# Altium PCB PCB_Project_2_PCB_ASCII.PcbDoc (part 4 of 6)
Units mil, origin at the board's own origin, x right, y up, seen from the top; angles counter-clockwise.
Board outline 3900 x 7800 mil, 6 copper layers (Top Layer, GND 1, Signal, Power, GND 2, Bottom Layer), stack 62.1 mil thick; 636 components, 334 nets, 1830 pads, 1401 vias.
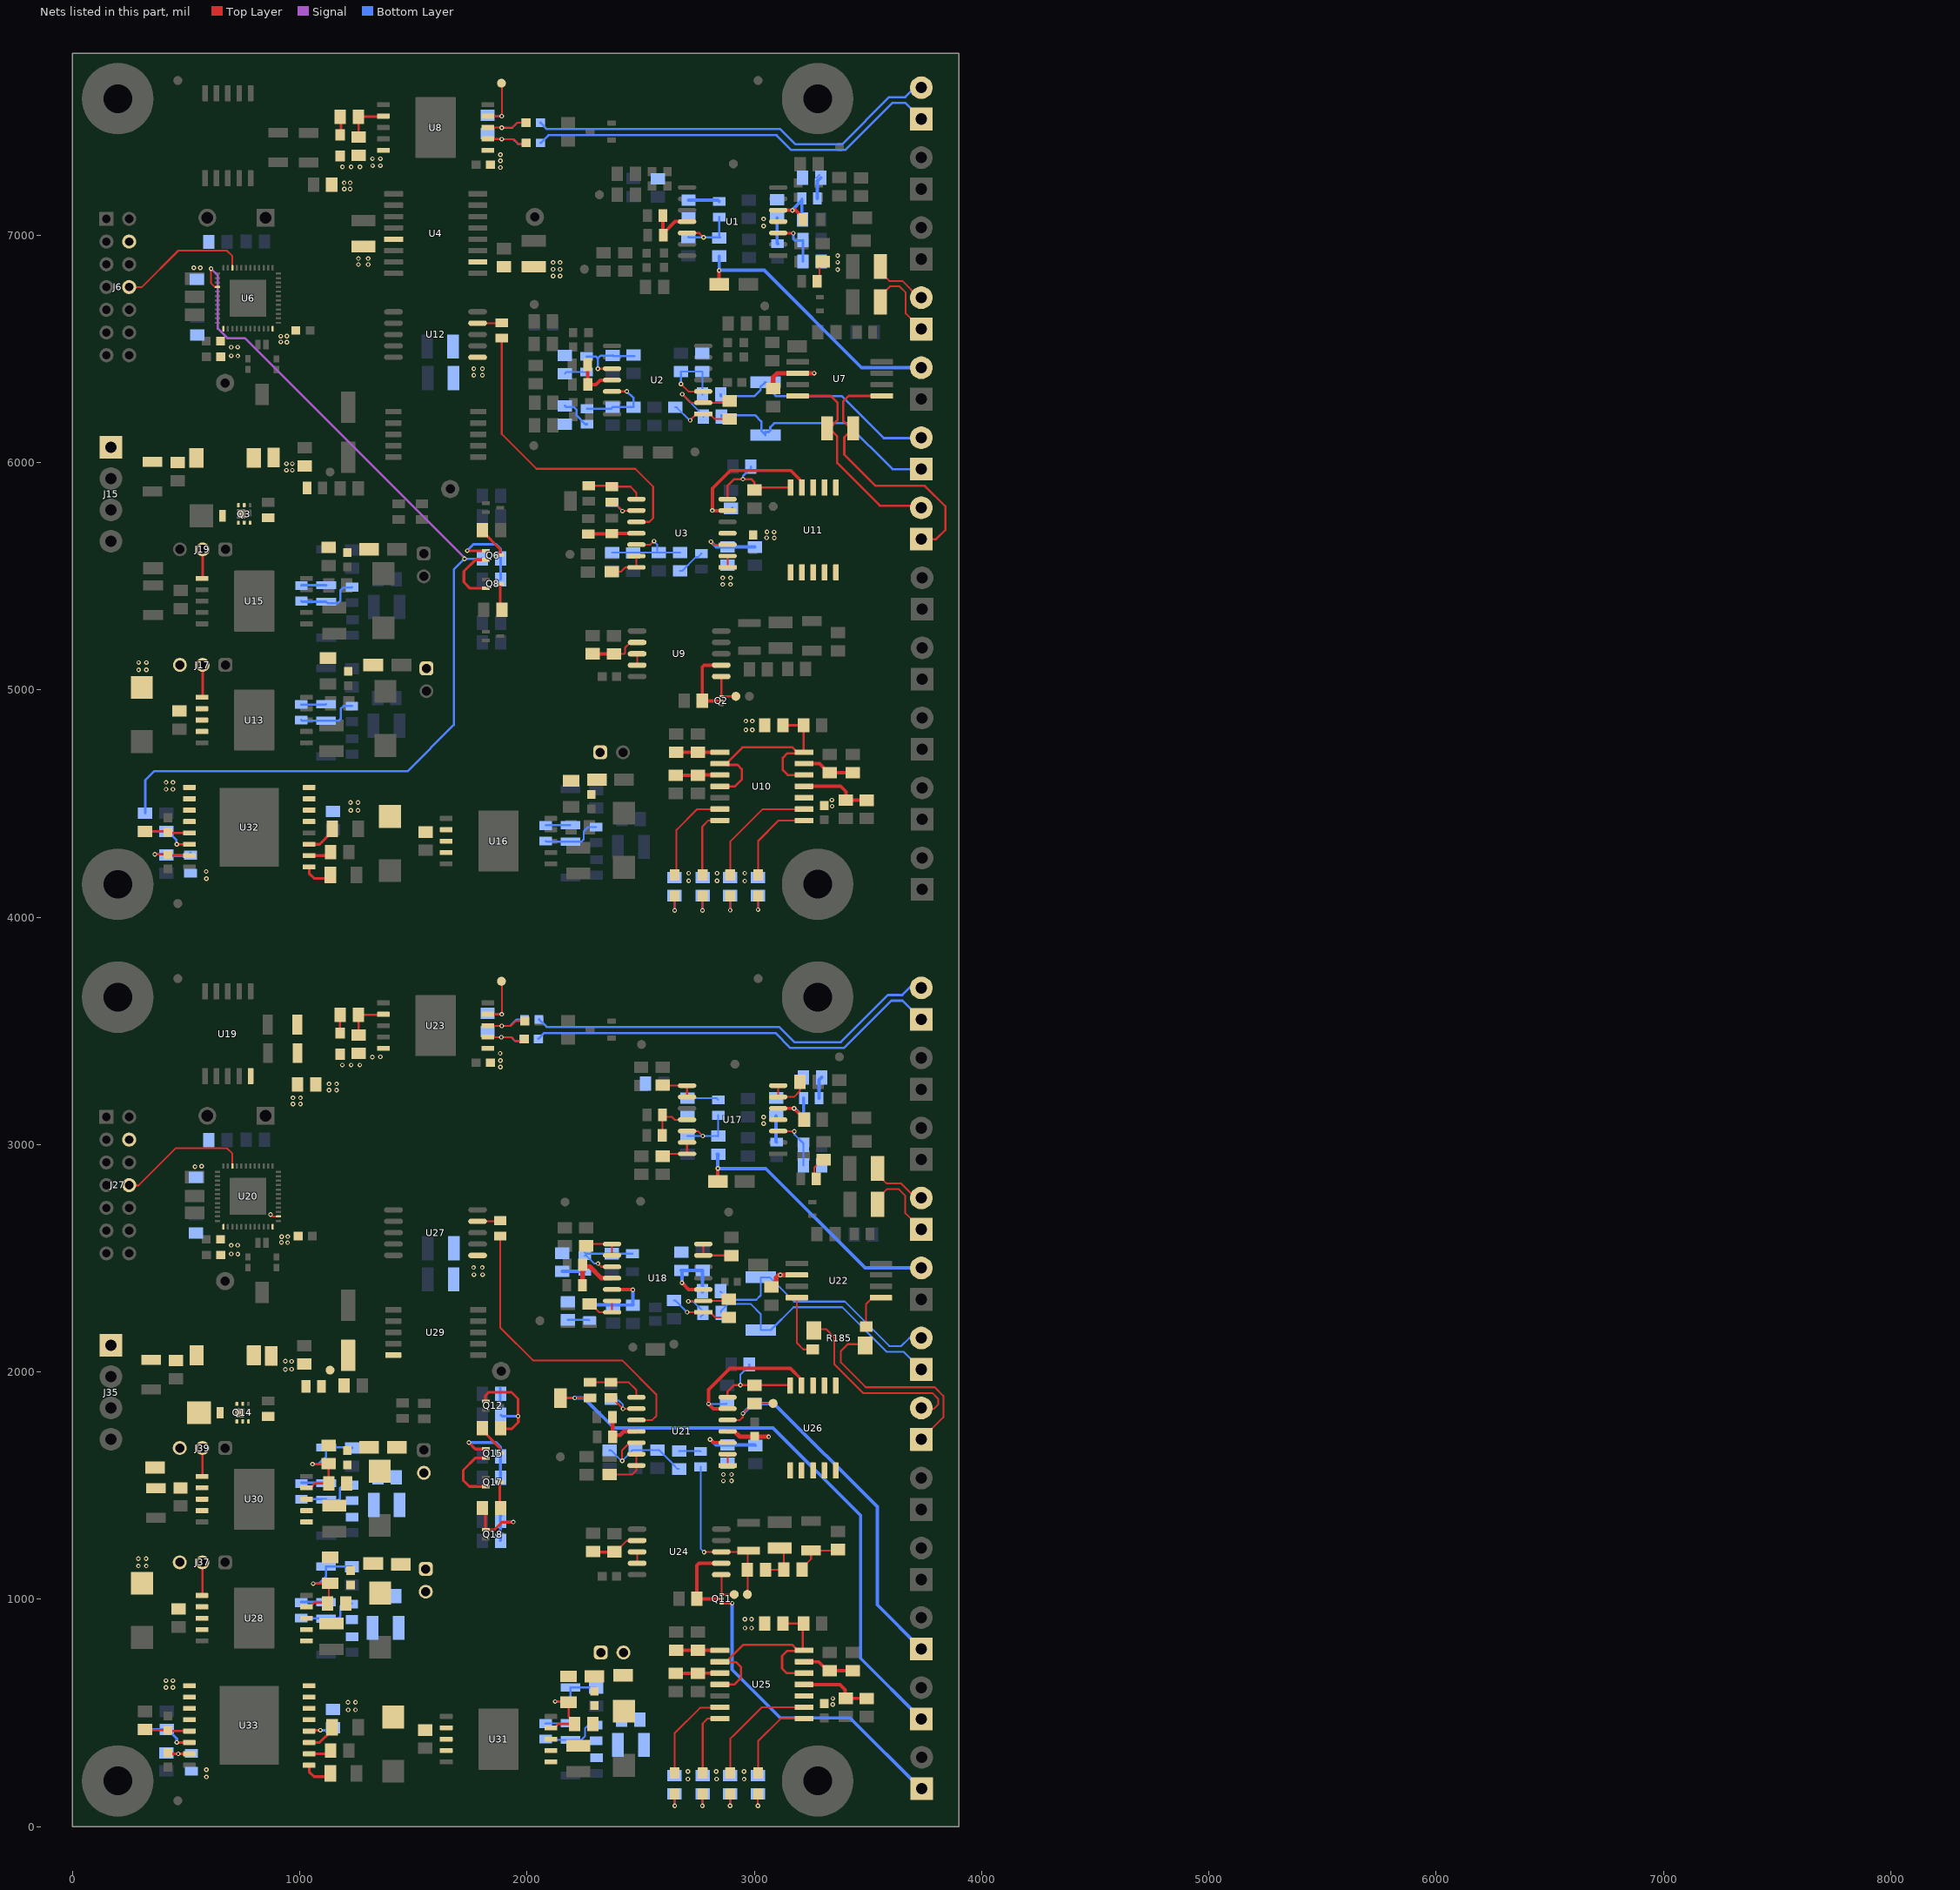
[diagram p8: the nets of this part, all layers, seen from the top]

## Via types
v1: diameter 20, hole 10, Top Layer to Bottom Layer, tented both sides, 1161 vias
v2: diameter 19.68, hole 7.87, Top Layer to Bottom Layer, 240 vias

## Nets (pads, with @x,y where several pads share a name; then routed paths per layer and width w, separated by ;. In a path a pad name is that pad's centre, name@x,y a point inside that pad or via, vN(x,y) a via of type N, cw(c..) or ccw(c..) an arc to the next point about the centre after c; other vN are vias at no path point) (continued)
NetC95_2: C95.2 R204.2 R206.2 TP57.1 U24.3 | length 793.4
  Top Layer w8: v1(2779.66,1207.33) 2780.26,1207.93 2848.17,1207.93 2854.71,1214.47 U24.3@2860.65,1208.53 ; U24.3@2854.71,1208.53 U24.3@2860.65,1208.53 ; R204.2@2970.75,1133.31 C95.2@2970.75,1214.47 ; TP57.1@2970.79,1010.82 TP57.1@2970.91,1010.94 ; TP57.1@2970.91,1019.89 2970.91,1127.69 2970.91,1133.31 R204.2@2972.21,1134.62 ; C95.2@2975.28,1214.47 C95.2@2970.75,1214.47 ; R204.2@2984.42,1141.46 R204.2@2988.43,1137.45 ; U24.3@2860.65,1208.53 2964.81,1208.53 C95.2@2970.75,1214.47
  Bottom Layer w8: R206.2@2764.02,1582.55 2764.02,1222.97 v1(2779.66,1207.33)
NetC96_1: C96.1 R202.2 R203.1 | length 220.9
  Top Layer w8: R203.1@3217.22,1137.66 3217.22,1144.55 3249.6,1176.93 3249.6,1213.81 C96.1@3250.22,1214.44 ; C96.1@3253.84,1222.04 C96.1@3257.62,1218.26 ; C96.1@3257.62,1214.44 C96.1@3257.62,1218.26 ; R202.2@3370.37,1231.17 3353.63,1214.44 3261.44,1214.44 C96.1@3257.62,1218.26
NetC97_1: C97.1 R203.2 R204.1 | length 184.3
  Top Layer w8: R204.1@3049.81,1129.86 3130.58,1129.86 R203.2@3130.78,1130.06 3130.78,1207.14 C97.1@3112.3,1225.62
NetC102_1: C102.1 R236.1 R237.1 TP62.1 U29.10
NetC104_1: C104.1 C105.1 C106.1 C107.1 C108.1 J36.2 R238.2 TP63.1 U28.6 U28.7 U28.8
NetC104_2: C104.2 D18.2 R239.1 R243.2 U28.9 | length 491
  Top Layer w8: C104.2@1128.04,984.27 1128.04,1063.82 1133.1,1068.88 R239.1@1134.69,1070.47
  Top Layer w10: U28.9@1029.99,966.93 1047.12,966.93 1065.88,985.68 C104.2@1122.35,985.68 ; v1(1059.83,1068.88) R239.1@1133.1,1068.88
  Bottom Layer w10: v1(1059.83,1068.88) 1085.16,1068.88 1116.03,1099.75 1116.03,1144.44 D18.2@1116.21,1144.62 1227.84,1144.62 R243.2@1230.01,1142.46
NetC107_2: C107.2 C108.2 R241.1 R242.1
NetC111_1: C111.1 C112.1 C113.1 C114.1 C115.1 J38.2 R244.2 TP66.1 U30.6 U30.7 U30.8
NetC111_2: C111.2 D21.2 R246.1 R254.2 U30.9 | length 493.2
  Top Layer w10: U30.9@1030.71,1490.09 1047.84,1490.09 1067.47,1509.73 1127.14,1509.73 C111.2@1127.82,1509.05 1127.82,1595.74 R246.1@1127.05,1596.51 1125.05,1594.51 v1(1056.65,1594.51)
  Bottom Layer w10: v1(1056.65,1594.51) 1083.54,1594.51 1116.17,1627.14 1116.17,1667.03 D21.2@1116.93,1667.78 1228.56,1667.78 R254.2@1230.72,1665.62
NetC114_2: C114.2 C115.2 R249.1 R251.1
NetC116_2: C116.2 Q12.1 R245.1 R250.2 | length 552
  Top Layer w12: Q12.1@1817.29,1868.81 1816.75,1869.35 1816.75,1895.47 1831.8,1910.52 1932.28,1910.52 1960.89,1881.92 v1(1960.89,1805.46) 1962.06,1804.28 1962.06,1778.43 1934.13,1750.5 R250.2@1882.44,1750.5
  Bottom Layer w12: R245.1@1882.54,1837.92 C116.2@1882.54,1928.92 ; R245.1@1886,1810 1890.54,1805.46 v1(1960.89,1805.46)
NetC117_1: C117.1 R125.1 R127.2 U32.7 | length 322.3
  Top Layer w8: C117.1@420.09,4276.3 C117.1@420.72,4275.67
  Top Layer w10: v1(363.34,4276.3) C117.1@420.09,4276.3 ; C117.1@425.64,4270.75 U32.7@515.12,4270.75
  Top Layer w12: C117.1@420.72,4275.67 C117.1@425.64,4270.75
  Bottom Layer w8: R127.2@410.37,4276.3 R127.2@413.58,4273.09
  Bottom Layer w10: v1(363.34,4276.3) R127.2@410.37,4276.3
  Bottom Layer w12: R127.2@414.17,4284.17 427.6,4270.75 507.22,4270.75 R125.1@520.02,4283.54
NetC120_1: C120.1 C121.1 D20.1 J39.3 TP68.1 U30.2 U30.3 U30.4
NetC122_1: C122.1 Q18.1 R259.1 R260.2 | length 566.2
  Top Layer w12: R259.1@1801.57,1399.44 1817.29,1383.71 1817.29,1304.26 Q18.1@1821.18,1304.26 ; Q18.1@1819.44,1306 1856.73,1306 1888.67,1337.93 v1@1937.85,1337.93
  Bottom Layer w12: R260.2@1882.44,1282.82 1882.44,1369.31 C122.1@1886.62,1365.13 ; R260.2@1882.54,1282.69 1882.54,1369.18 C122.1@1886.72,1365 ; R260.2@1883.69,1257.45 1883.69,1343.94 1887.86,1339.76 v1@1939.65,1339.76
  other v1: 1940,1340.09
NetC123_1: C123.1 C124.1 C125.1 C126.1 C127.1 J40.2 R261.2 TP70.1 U31.6 U31.7 U31.8
NetC123_2: C123.2 D23.2 R262.1 R266.2 U31.9 | length 511.7
  Top Layer w10: U31.9@2104.9,434.68 2122.02,434.68 2139.57,452.23 C123.2@2209.59,452.23 2209.59,458.73 2183.45,484.87 2183.45,546.66 R262.1@2183.74,546.95 2180.32,550.38 v1(2123.84,550.38)
  Bottom Layer w10: v1(2123.84,550.38) 2171.99,550.38 2191.12,569.51 D23.2@2191.12,612.38 2302.75,612.38 R266.2@2304.91,610.22
NetC126_2: C126.2 C127.2 R264.1 R265.1
NetC130_1: C130.1 U32.11 | length 133.9
  Top Layer w12: U32.11@1042.12,4320.75 1088.27,4320.75 1135.71,4368.19 C130.1@1135.71,4388.88
NetC131_1: C131.1 U32.9 | length 137.3
  Top Layer w12: U32.9@1042.12,4220.75 1042.12,4192.03 1063.77,4170.38 1121.09,4170.38 C131.1@1135.71,4185
NetC132_1: C132.1 R252.2 U32.5 | length 197.4
  Top Layer w10: R252.2@320.45,4377.45 417.77,4377.45 C132.1@420.72,4374.5 424.47,4370.75 U32.5@515.12,4370.75
NetC133_2: C133.2 U33.12 | length 111.2
  Top Layer w12: U33.12@1041.87,420.29 1045.62,424.05 v1(1090.99,424.05)
  Bottom Layer w12: v1@1090.9,424.18 1136.24,424.18 C133.2@1146.96,434.91
NetC134_1: C134.1 R256.1 R268.2 U33.7 | length 195.1
  Top Layer w12: C134.1@420.46,325.22 425.38,320.29 v1(466.25,320.29) U33.7@514.87,320.29
  Bottom Layer w12: R268.2@413.82,333.85 427.24,320.43 466.15,320.43 R256.1@506.87,320.43
NetC135_1: C135.1 U33.11 | length 134
  Top Layer w12: U33.11@1041.87,370.29 1088.1,370.29 1135.46,417.65 C135.1@1135.46,438.42
NetC136_1: C136.1 U33.9 | length 137.3
  Top Layer w12: U33.9@1041.87,270.29 1041.87,241.57 1063.51,219.93 1120.84,219.93 C136.1@1135.46,234.55
NetC137_1: C137.1 R270.2 U33.5 | length 197.4
  Top Layer w10: R270.2@320.19,426.99 323.14,424.05 C137.1@420.46,424.05 424.22,420.29 U33.5@514.87,420.29
NetD1_2: D1.2 R62.1 | length 75.2
  Top Layer w8: R62.1@1179.6,7518.92 R62.1@1182.3,7516.22
  Top Layer w10: D1.2@1182.3,7444.82 R62.1@1182.3,7516.22
NetD2_1: D2.1 R78.1 | length 121.7
  Top Layer w8: v1@3017.09,4033.39 D2.1@3017.09,4093.19
  Bottom Layer w8: v1(3016.73,4033.04) 3016.73,4094.43 R78.1@3017.09,4094.79
NetD2_2: D2.2 U10.1 | length 392.1
  Top Layer w8: D2.2@3025.09,4185.71 3017.02,4193.78 3017.02,4335.12 3107.36,4425.46 U10.1@3219,4425.46
NetD3_1: D3.1 R90.1 | length 126.3
  Top Layer w8: v1@2894.38,4030.9 D3.1@2894.38,4093.19
  Bottom Layer w8: v1(2894.27,4030.79) 2894.27,4094.67 R90.1@2894.38,4094.79
NetD3_2: D3.2 U10.2 | length 534
  Top Layer w8: D3.2@2902.38,4185.71 2894.38,4193.71 2894.38,4332.64 3037.2,4475.46 U10.2@3219,4475.46
NetD4_1: D4.1 R93.1 | length 128.1
  Top Layer w8: v1@2772.69,4030.55 D4.1@2772.69,4092.64
  Top Layer w20: D4.1@2772.69,4092.64 D4.1@2773.24,4093.19
  Bottom Layer w8: v1(2772.14,4030) 2772.14,4093.68 R93.1@2773.24,4094.79
NetD4_2: D4.2 U10.14 | length 305.5
  Top Layer w8: D4.2@2781.24,4185.71 2771.23,4195.71 2771.23,4397.97 2798.72,4425.46 U10.14@2848.92,4425.46
NetD5_1: D5.1 R100.1 | length 128.6
  Top Layer w8: v1(2649.99,4030) D5.1@2649.99,4093.19
  Bottom Layer w8: R100.1@2648.42,4094.79 2649.99,4093.21 v1(2649.99,4030)
NetD5_2: D5.2 U10.13 | length 427.1
  Top Layer w8: D5.2@2657.99,4185.71 2657.99,4383.99 2749.46,4475.46 U10.13@2848.92,4475.46
NetD6_1: D6.1 R113.2 | length 109.8
  Bottom Layer w10: R113.2@1007.16,4935.38 1114.45,4935.38 D6.1@1116.21,4937.14
NetD7_2: D7.2 R113.1 R114.2 | length 276.5
  Bottom Layer w10: R113.1@1007.16,4867.27 1010.11,4864.32 D7.2@1116.21,4864.32 1172.78,4864.32 1181,4872.55 1181,4916.53 1193.07,4928.61 R114.2@1230.01,4928.61
NetD8_2: D8.2 L1.2 Q3.1 Q3.2 Q3.5 Q3.6 Q3.8 TP32.1
NetD9_1: D9.1 R119.2 | length 112.3
  Bottom Layer w12: R119.2@1007.88,5458.54 1009.64,5460.3 D9.1@1116.93,5460.3 D9.1@1115.17,5458.54
NetD10_2: D10.2 R119.1 R120.2 | length 282
  Bottom Layer w10: R119.1@1007.88,5390.43 1010.82,5387.49 D10.2@1116.93,5387.49 1123.22,5381.2 1168.45,5381.2 1179.03,5391.77 1179.03,5436.3 1192.34,5449.62 1228.57,5449.62 R120.2@1230.72,5451.77
NetD11_1: D11.1 R136.2 | length 109.8
  Bottom Layer w8: R136.2@2082.01,4403.14 2083.77,4404.9 D11.1@2191.06,4404.9
NetD12_2: D12.2 R136.1 R137.2 | length 271
  Bottom Layer w8: R136.1@2082.01,4335.03 2084.95,4332.08 D12.2@2191.06,4332.08 2239.44,4332.08 2250,4342.64 2250,4377.28 2269.08,4396.36 R137.2@2304.85,4396.36
NetD13_2: D13.2 R190.1 | length 76.5
  Top Layer w8: R190.1@1177.99,3567.37 R190.1@1179.5,3568.88
  Top Layer w10: R190.1@1177.99,3567.37 1177.99,3498.99 D13.2@1182.2,3494.78
NetD14_1: D14.1 R210.1 | length 105.4
  Top Layer w8: D14.1@3012,142 3016,138 v1(3016,92.06)
  Bottom Layer w8: v1(3016,92.06) 3016,145.2 3015.85,145.35 R210.1@3016.2,145.7
NetD14_2: D14.2 U25.1 | length 380.3
  Top Layer w8: D14.2@3017.09,235.71 3017.09,376.73 3115.4,475.05 3123.78,475.05 ; 3123.78,475.24 U25.1@3215.6,475.24
NetD15_1: D15.1 R217.1 | length 101.7
  Top Layer w8: v1(2894.01,92.06) 2894.01,137.02 D15.1@2896,139
  Bottom Layer w8: R217.1@2893.5,145.7 2893.39,145.59 2894.01,144.96 v1(2894.01,92.06)
NetD15_2: D15.2 U25.2 | length 529.2
  Top Layer w8: D15.2@2894.38,235.71 2894.38,386.03 2912.96,404.61 3033.59,525.24 U25.2@3215.6,525.24
NetD16_1: D16.1 R223.1 | length 105.6
  Top Layer w8: D16.1@2769,142 2772.03,138.97 v1(2772.03,92.06)
  Bottom Layer w8: v1(2772.03,92.06) 2772.03,143.82 2771.25,144.6 R223.1@2772.35,145.7
NetD16_2: D16.2 U25.14 | length 298.3
  Top Layer w8: D16.2@2773.24,235.71 2773.24,454 2784.01,464.78 ; 2784.78,465.59 2794.43,475.24 U25.14@2845.52,475.24
NetD17_1: D17.1 R230.1 | length 103.1
  Top Layer w8: D17.1@2649,140 2650.05,138.95 v1(2650.05,92.06)
  Bottom Layer w8: R230.1@2647.53,145.7 2650.05,143.19 v1(2650.05,92.06)
NetD17_2: D17.2 U25.13 | length 418.6
  Top Layer w8: D17.2@2649.99,235.71 2649.99,411.72 2761.15,522.87 2843.16,522.87 U25.13@2845.52,525.24
NetD18_1: D18.1 R240.2 | length 109.8
  Bottom Layer w10: R240.2@1006.06,988.1 1113.35,988.1 D18.1@1115.11,989.86
NetD19_2: D19.2 R240.1 R241.2 | length 276.5
  Bottom Layer w10: R240.1@1006.06,919.99 1009,917.04 1115.11,917.04 1171.67,917.04 1179.9,925.27 1179.9,969.25 1191.97,981.33 R241.2@1228.9,981.33
NetD20_2: D20.2 L2.2 Q14.1 Q14.2 Q14.5 Q14.6 Q14.8 TP67.1
NetD21_1: D21.1 R248.2 | length 107.3
  Bottom Layer w12: R248.2@1008.54,1513.02 D21.1@1115.83,1513.02
NetD22_2: D22.2 R248.1 R249.2 | length 282
  Bottom Layer w10: R248.1@1006.77,1443.15 1009.72,1440.21 1115.83,1440.21 1122.12,1433.92 1167.35,1433.92 1177.92,1444.49 1177.92,1489.02 1191.23,1502.34 1227.47,1502.34 R249.2@1229.62,1504.49
NetD23_1: D23.1 R263.2 | length 109.8
  Bottom Layer w8: R263.2@2081.65,452.81 2083.42,454.57 D23.1@2190.71,454.57
NetD24_2: D24.2 R263.1 R264.2 | length 271
  Bottom Layer w8: R263.1@2081.65,384.7 2084.6,381.76 2239.09,381.76 2255.64,398.31 2255.64,432.96 2268.73,446.04 R264.2@2304.5,446.04
NetJ2_1: J2.1 R18.1 R19.1 | length 1067.5
  Bottom Layer w10: R19.1@2855.47,6201.45 2855.47,6207.95 3002.98,6207.95 3031.02,6179.91 3031.02,6138.78 R18.1@3049.29,6120.5 3049.29,6133.76 3063.44,6133.76 3070.77,6141.09 3070.77,6155.24 3087.93,6172.39 3406.55,6172.39 3608.5,5970.45 J2.1@3735,5970.45
NetJ2_2: J2.2 R16.1 R18.2 | length 1033.3
  Bottom Layer w10: R16.1@2852.63,6298.77 2852.63,6292.27 3001.33,6292.27 3027.12,6318.05 3027.12,6332.2 3047.71,6352.79 R18.2@3049.29,6352.79 3069.02,6333.06 3069.02,6318.05 3094.81,6292.27 3384.63,6292.27 3569.74,6107.16 3733.72,6107.16 J2.2@3735,6108.45
NetJ4_1: J4.1 R37.2 | length 355.6
  Top Layer w8: R37.2@3554.93,6705.9 3554.93,6731.49 3598.25,6774.81 3638.71,6774.81 3666.58,6746.94 3666.58,6654.87 J4.1@3735,6586.45
NetJ4_2: J4.2 R35.2 | length 251.1
  Top Layer w8: R35.2@3554.93,6861.5 3554.93,6837.08 3593.9,6798.11 3651.51,6798.11 3725.17,6724.45 J4.2@3735,6724.45
NetJ5_2: J5.2 R44.1 TP12.1 | length 1192.7
  Top Layer w8: TP12.1@2845.25,6783.65 TP12.1@2846.04,6782.86
  Top Layer w15: TP12.1@2845.25,6783.65 v1(2845.25,6844.84)
  Bottom Layer w15: R44.1@2845.81,6907.8 2845.81,6845.4 v1(2845.25,6844.84) 3043.29,6844.84 3471.69,6416.45 J5.2@3735,6416.45
NetJ6_8: J6.8 U6.22 | length 581.8
  Top Layer w8: J6.8@250,6771.53 306.14,6771.53 466.4,6931.79 679.66,6931.79 704.21,6907.23 U6.22@704.21,6856.18
NetJ8_1: J8.1 R56.1 U7.1 | length 1230.5
  Top Layer w10: U7.1@3561.06,6292.56 3415.97,6292.56 3391,6267.59 3391,6184 3425.34,6149.66 R56.1@3435.04,6149.66 3396,6110.61 3396,6034.69 3533.69,5897 3750.75,5897 3841,5806.75 3841,5703 3800.45,5662.45 J8.1@3735,5662.45 J8.1@3727.16,5670.29
NetJ8_2: J8.2 R56.2 U7.8 | length 1032.9
  Top Layer w10: U7.8@3190.98,6292.56 3336.9,6292.56 3367,6262.46 3367,6186.54 R56.2@3330.12,6149.66 ; R56.2@3320.87,6149.66 R56.2@3330.12,6149.66 ; J8.2@3735,5800.45 J8.2@3744.55,5810 ; R56.2@3330.12,6149.66 3365,6114.77 3365,5997.95 3552.95,5810 J8.2@3744.55,5810 ; J8.2@3744.55,5810 3763.94,5810 J8.2@3763.94,5829.39 ; J8.2@3744.55,5810 J8.2@3763.94,5829.39 ; J8.2@3763.94,5829.39 3764.72,5830.17 3763.94,5830.95 J8.2@3763.94,5829.39
NetJ10_1: J10.1 R72.1 | length 1831.5
  Bottom Layer w10: R72.1@2059.89,7404.9 2060.87,7404.9 2095.1,7439.13 2139.95,7439.13 3097.8,7439.13 3162.44,7374.48 3400.57,7374.48 3607.85,7581.76 3663.69,7581.76 J10.1@3735,7510.45
NetJ10_2: J10.2 R71.1 | length 1818.4
  Bottom Layer w10: R71.1@2059.2,7494.1 2060.18,7494.1 2087.82,7466.46 2135.78,7466.46 3114.18,7466.46 3181.48,7399.17 3385.65,7399.17 3592.83,7606.35 3664.22,7606.35 3706.32,7648.45 J10.2@3735,7648.45
NetJ17_2: J17.2 U13.1 | length 144.2
  Top Layer w10: U13.1@570.15,4966.92 573.48,4970.26 J17.2@573.48,5109.78
NetJ19_2: J19.2 U15.1 | length 139.5
  Top Layer w10: U15.1@561.91,5490.09 U15.1@566.66,5490.09 ; U15.1@570.87,5490.09 U15.1@566.66,5490.09 ; J19.2@573.48,5617.78 573.48,5496.91 U15.1@566.66,5490.09
NetJ22_1: J22.1 R155.1 R156.1 | length 1144.4
  Bottom Layer w8: R156.1@2854.06,2260.5 2854.06,2267 2886.33,2299.28 2983.78,2299.28 3028.89,2254.17 R155.1@3028.89,2184.22 3072.86,2184.22 3173.34,2284.7 3386.82,2284.7 3582.91,2088.61 3657.5,2088.61 J22.1@3735,2011.1
NetJ22_2: J22.2 R153.1 R155.2 | length 1125.8
  Bottom Layer w8: R153.1@2851.79,2353.29 2887.89,2317.19 3008.96,2317.19 3028.89,2337.12 R155.2@3028.89,2416.5 3068.01,2416.5 3175.13,2309.38 3398.77,2309.38 3594.31,2113.84 3646.58,2113.84 3681.84,2149.1 J22.2@3735,2149.1
NetJ25_1: J25.1 R169.2 | length 353.2
  Top Layer w8: R169.2@3542.84,2737.45 3542.84,2763.04 3583.37,2803.57 3636.24,2803.57 3664.58,2775.24 3664.58,2697.52 J25.1@3735,2627.1
NetJ25_2: J25.2 R168.2 | length 259.5
  Top Layer w8: R168.2@3542.84,2893.05 3542.84,2868.63 3583.16,2828.32 3646.89,2828.32 3710.1,2765.1 J25.2@3735,2765.1
NetJ26_2: J26.2 R177.1 TP47.1 | length 1191.5
  Top Layer w8: TP47.1@2839.68,2848.23 2840.8,2849.35 TP47.1@2839.88,2850.27
  Top Layer w15: TP47.1@2839.88,2850.27 v1(2839.88,2894.75)
  Bottom Layer w15: R177.1@2841.87,2956.82 2837.84,2956.82 2840.8,2953.86 2839.88,2952.94 v1(2839.88,2894.75) 3050.76,2894.75 3488.41,2457.1 J26.2@3735,2457.1
NetJ27_8: J27.8 U20.22 | length 586.6
  Top Layer w8: J27.8@250,2820.53 291.47,2820.53 454.73,2983.78 680.62,2983.78 704.21,2960.19 U20.22@704.21,2905.18
NetJ29_1: J29.1 R185.2 | length 939.6
  Top Layer w8: R185.2@3514.7,2122.08 3411.19,2122.08 3381.28,2092.17 3381.28,2041.55 3490.32,1932.51 3793.91,1932.51 3832,1894.42 3832,1800.1 J29.1@3735,1703.1
NetJ29_2: J29.2 R185.1 | length 822.7
  Top Layer w8: R185.1@3289.9,2187.83 3316.17,2187.83 3351.52,2152.48 3351.52,2034.93 3480.34,1906.11 3784.89,1906.11 3809,1882 3809,1856.46 3791.01,1838.47 3737.63,1838.47 J29.2@3735,1841.1
NetJ31_1: J31.1 R199.1 | length 1832.9
  Bottom Layer w10: R199.1@2050.01,3464.71 2051,3464.71 2076.53,3490.25 3093,3490.25 3157.65,3425.6 3395.78,3425.6 3603.06,3632.88 3652.37,3632.88 3723.69,3561.57 J31.1@3730.21,3561.57
NetJ31_2: J31.2 R197.1 | length 1822.4
  Bottom Layer w10: R197.1@2052.6,3550.49 2053.58,3550.49 2086.48,3517.58 2143.94,3517.58 3109.39,3517.58 3176.69,3450.29 3380.85,3450.29 3588.04,3657.48 3651.42,3657.48 3693.51,3699.57 J31.2@3730.21,3699.57
NetJ32_1: J32.1 Q11.3@2856.51,982.19 | length 1389.4
  Top Layer w10: Q11.3@2856,982.16 2902.01,982.16 v1(2902.87,983.01)
  Bottom Layer w15: v1(2902.87,983.01) 2902.87,690.78 3115.33,478.31 3421.69,478.31 J32.1@3735,165
NetJ33_1: J33.1 R222.1 R224.2 TP60.1 U21.5 | length 1742.6
  Top Layer w8: U21.5@2882.73,1788.47 2937.38,1788.47 2950.45,1801.55 v1(2950.45,1817.23) 2950.45,1817.77 2988.43,1855.74 2988.43,1856.46 2993.5,1861.54 R222.1@3000.72,1861.54 TP60.1@3083.06,1861.54
  Bottom Layer w15: v1(2950.45,1817.23) 2994.22,1861 R224.2@3000.72,1861 3086.87,1861 3541,1406.87 3541,975.91 J33.1@3735,781.91
NetJ34_1: J34.1 R229.2 TP61.1 | length 2608.7
  Top Layer w10: TP61.1@2147.16,1884.31 2148.74,1885.9 v1(2210,1885.9) R229.2@2277.42,1885.9
  Bottom Layer w15: v1(2210,1885.9) 2250.65,1885.9 2382.9,1753.65 3082.67,1753.65 3468,1368.31 3468,740.51 J34.1@3735,473.51
NetJ37_2: J37.2 U28.1 | length 146.5
  Top Layer w10: U28.1@570.15,1016.93 572.38,1019.15 J37.2@572.38,1162.5
NetJ39_2: J39.2 U30.1 | length 126
  Top Layer w8: U30.1@570.87,1540.09 U30.1@572.38,1541.6
  Top Layer w10: U30.1@572.38,1541.6 J39.2@572.38,1665.5
NetQ2_1: Q2.1@2855.63,4971.35 TP23.1 U9.1 | length 151.3
  Top Layer w8: U9.1@2854.71,5058.53 2855.63,5057.61 Q2.1@2855.63,4971.35 TP23.1@2919.34,4971.35
NetQ2_2: Q2.2@2855.63,4951.67 R80.2 U9.2 | length 319.1
  Top Layer w10: 2832.01,4951.67 Q2.2@2855.63,4951.67
  Top Layer w15: 2832.01,4951.67 2772.14,4951.67 R80.2@2771.23,4952.57 2771.23,5099.75 2780.02,5108.53 U9.2@2854.71,5108.53
NetQ3_3: Q3.3 R121.1
NetQ6_1: Q6.1 R128.2 R130.2 | length 380.9
  Top Layer w8: v1(1737.31,5611.83) v1@1737.41,5611.73 ; Q6.1@1814.56,5611.73 Q6.1@1815.35,5610.95
  Top Layer w12: v1@1737.41,5611.73 Q6.1@1814.56,5611.73
  Bottom Layer w12: v1(1737.31,5611.83) 1737.31,5612.36 1764.92,5639.97 1865.03,5639.97 1884.04,5620.96 R128.2@1884.04,5577.66 R130.2@1884.04,5485
NetQ6_2: Q6.2 Q8.2 | length 273.2
  Top Layer w12: Q8.2@1819.44,5446.34 1750.08,5446.34 1722.86,5473.56 1722.86,5521.2 1773.93,5572.27 Q6.2@1819.44,5572.27
NetQ6_3: Q6.3 R126.1 | length 146
  Top Layer w12: R126.1@1806.74,5704.8 R126.1@1804.59,5702.65 1804.59,5696.15 1882.44,5618.3 Q6.3@1882.44,5591.95
NetQ8_3: Q8.3 R132.2 | length 115
  Top Layer w12: Q8.3@1882.44,5466.02 1882.44,5352.87 R132.2@1883.72,5351.59
NetQ11_1: Q11.1@2856.51,1021.56 TP58.1 U24.1 | length 151.3
  Top Layer w8: U24.1@2855.08,1108.71 2856,1107.79 2856,1021.53 TP58.1@2919.71,1021.53
NetQ11_2: Q11.2@2856.51,1001.88 R205.2 U24.2 | length 366.7
  Top Layer w10: 2832.37,1001.84 Q11.2@2856,1001.84
  Top Layer w15: 2832.37,1001.84 2747.77,1001.84 2747.77,1149.75 2756.56,1158.53 U24.2@2854.71,1158.53
NetQ14_3: Q14.3 R253.1
NetQ15_1: Q15.1 R255.2 R257.2 | length 373.3
  Top Layer w12: v1(1744.51,1689.65) 1773.1,1661.06 Q15.1@1819.73,1661.06
  Bottom Layer w12: v1(1744.51,1689.65) 1864.67,1689.65 1883.69,1670.64 R255.2@1883.69,1651.43 ; R257.2@1882.54,1559.92 R257.2@1883.69,1561.06 ; R255.2@1882.54,1652.58 R255.2@1883.69,1651.43 ; R257.2@1883.69,1534.68 R257.2@1883.69,1561.06 ; R257.2@1883.69,1561.06 R255.2@1883.69,1651.43
NetQ15_2: Q15.2 Q17.2 | length 277.6
  Top Layer w12: Q17.2@1819.44,1496.34 1746.83,1496.34 1719.89,1523.27 1719.89,1568.23 1773.93,1622.27 Q15.2@1819.44,1622.27
NetQ15_3: Q15.3 R250.1 | length 146
  Top Layer w12: R250.1@1804.59,1752.65 1802.44,1750.5 1802.44,1744 1880.28,1666.15 Q15.3@1880.28,1639.8
NetQ17_3: Q17.3 R259.2 | length 115
  Top Layer w12: Q17.3@1880.28,1513.87 1880.28,1400.72 R259.2@1881.57,1399.44
NetR1_2: R1.2 R2.2 | length 98.9
  Top Layer w8: R2.2@3276.65,6797.17 3287.77,6808.3 3287.77,6873.12 3297.65,6883 R1.2@3302,6883
NetR3_1: R3.1 R6.2 | length 115.2
  Bottom Layer w15: R3.1@3100.33,7076.04 3100.33,6963.96 R6.2@3102.56,6961.73
NetR4_2: R4.2 R5.1 U1.11 | length 212.6
  Top Layer w15: R5.1@2598.46,7085 2598.46,7004.45 2599.65,7003.27 2599.65,7007.3 2651.53,7059.19 U1.11@2704.48,7059.19
NetR7_2: R7.2 R8.1 U3.11 | length 209.4
  Top Layer w15: R7.2@2273.39,5686.53 2273.84,5686.08 2373.79,5686.08 2376.18,5688.47 U3.11@2481.65,5688.47
NetR9_1: R9.1 R12.2 U3.3 | length 281.9
  Top Layer w8: v1(2809.22,5651.68) 2822.42,5638.47 U3.3@2882.73,5638.47
  Bottom Layer w15: v1(2809.22,5651.68) 2832.42,5628.47 R9.1@2882.73,5628.47 3001.43,5628.47 R12.2@3002.19,5627.72
NetR11_1: R11.1 R13.2 U1.3 | length 232.4
  Top Layer w12: U1.3@3105.56,7009.19 3106.32,7008.42 v1(3171.77,7008.42)
  Bottom Layer w12: v1(3171.77,7008.42) 3171.77,6983.26 3180.02,6975 3211.22,6975 R13.2@3214.02,6977.8 R11.1@3214.02,6883.89
NetR14_1: R14.1 R15.2 R16.2 U2.3 | length 359.6
  Top Layer w8: v1(2677.57,6345.4) 2710.52,6312.45 U2.3@2775.45,6312.45
  Bottom Layer w8: v1(2677.57,6345.4) 2677.57,6398.85 R15.2@2678,6399.28 2770.74,6399.28 2772.63,6397.38 R16.2@2772.63,6298.77
NetR17_1: R17.1 R23.2 U2.1 | length 283.1
  Top Layer w8: v1(2718.29,6185.37) 2745.32,6212.45 U2.1@2775.45,6212.45 2804.47,6212.45 2826.47,6190.45 R23.2@2891.06,6190.45 R23.2@2891.12,6190.51
  Bottom Layer w8: R17.1@2652.11,6242.53 2658.61,6242.53 2715.77,6185.37 v1(2718.29,6185.37)
NetR19_2: R19.2 R23.1 U2.2 | length 363.5
  Top Layer w8: v1(2683.31,6300.1) 2720.97,6262.45 U2.2@2775.45,6262.45 2883.06,6262.45 R23.1@2891.06,6270.45
  Bottom Layer w8: v1(2683.31,6300.1) 2775.47,6207.95 R19.2@2775.47,6201.45
NetR20_1: R20.1 R22.2 U2.11 | length 200.9
  Top Layer w15: R20.1@2267.08,6428.67 2267.08,6343.74 R22.2@2268.26,6342.56 2302.89,6342.56 2321.91,6361.58 2373.51,6361.58 U2.11@2374.37,6362.45
NetR24_1: R24.1 R27.2 | length 114
  Bottom Layer w8: R24.1@3273.94,7252.3 R24.1@3285.94,7264.3
  Bottom Layer w15: R27.2@3277.7,7161.33 3277.7,7237.62 R24.1@3292.38,7252.3
NetR26_1: R26.1 R27.1 R30.2 U1.5 | length 282.7
  Top Layer w15: U1.5@3103,7108 3104.09,7109.09 3167.91,7109.09 v1(3168,7109) 3182.05,7109 3214,7077.05 R26.1@3214,7075
  Bottom Layer w8: v1(3168,7109) v1@3168,7111.67 ; R30.2@3209.59,7078.41 3213.11,7074.89 R30.2@3213.11,7068.39 ; R27.1@3209.59,7153.26 R27.1@3209.59,7161.33
  Bottom Layer w15: v1@3168,7111.67 3209.59,7153.26 R30.2@3209.59,7078.41
NetR40_1: R40.1 R42.2 | length 137.6
  Bottom Layer w15: R40.1@2711.01,7154.43 2839.1,7154.43 R42.2@2845.81,7147.72
NetR42_1: R42.1 R44.2 R45.2 U1.12 | length 309.9
  Top Layer w10: U1.12@2704.48,7009.19 2757.81,7009.19 v1(2777,6990) v1@2778,6989
  Bottom Layer w10: R45.2@2711,6991 2712,6990 v1(2777,6990) R44.2@2845.81,6990 ; R42.1@2845.81,7079.61 R44.2@2845.81,6990 ; R44.2@2849,6990 R44.2@2845.81,6990
NetR48_1: R48.1 R51.2 | length 145.8
  Bottom Layer w10: R48.1@2167.2,6249 2172.58,6243.62 2207.2,6243.62 2218.67,6232.16 2218.67,6205.65 2256.02,6168.3 R51.2@2264.09,6168.3
NetR50_1: R50.1 R51.1 R53.2 U2.12 | length 355.1
  Top Layer w8: U2.12@2374.37,6312.45 U2.12@2374.51,6312.58
  Top Layer w10: U2.12@2374.51,6312.58 v1(2439.23,6312.58)
  Bottom Layer w10: R51.1@2264.09,6236.41 2370.41,6236.41 R53.2@2377.62,6243.62 R50.1@2469.7,6243.63 2469.7,6282.12 v1(2439.23,6312.58)
NetR60_1: R60.1 R62.2 U8.7 | length 195.3
  Top Layer w8: R62.2@1259.6,7518.92 R62.2@1261.82,7521.14
  Top Layer w10: R60.1@1259.6,7434.4 R62.2@1259.6,7518.91 ; R62.2@1261.82,7521.14 1314.44,7521.14 1368.22,7521.14 U8.7@1369.08,7522
NetR61_1: R61.1 TP19.1 U8.4 | length 266.1
  Top Layer w8: U8.4@1828.92,7522 1829.5,7522.57 1888.7,7522.57 v1(1889.27,7523.15) 1889.46,7523.34 1889.46,7663.75 TP19.1@1889.65,7663.94
  Bottom Layer w8: R61.1@1825.27,7523.89 1826.01,7523.15 v1(1889.27,7523.15)
NetR63_1: R63.1 R67.2 | length 98.4
  Bottom Layer w8: R63.1@2167.2,6390.59 2174.76,6398.15 R67.2@2262.47,6398.15
NetR65_1: R65.1 R67.1 R70.2 U2.10 | length 322.7
  Top Layer w8: v1(2312,6412) 2312.22,6412.22 2370.78,6412.22 U2.10@2371,6412
  Bottom Layer w10: R67.1@2262.47,6466.26 2303.44,6466.26 2312,6457.7 ; v1(2312,6412) 2312,6457.7 ; R70.2@2374.7,6470.3 2324.59,6470.3 2312,6457.7 ; R70.2@2377.36,6470.86 2380.22,6468 R65.1@2473,6468
NetR66_2: R66.2 R71.2 U8.3 | length 295.9
  Top Layer w8: U8.3@1828.2,7473.17 1828.86,7472.5 1935.65,7472.5 1957.56,7494.42 R66.2@1996.55,7494.42 R66.2@1998.46,7494.42
  Bottom Layer w8: v1(1889.17,7471.84) 1935.33,7471.84 1957.59,7494.1 R71.2@1996.2,7494.1
NetR69_2: R69.2 R72.2 U8.2 | length 303.2
  Top Layer w8: U8.2@1828.2,7423.17 1828.84,7422.53 1888.61,7422.53 v1(1889.24,7421.89) 1941.99,7421.89 1962.8,7401.09 1993.44,7401.09 R69.2@2000.98,7408.63
  Bottom Layer w8: v1(1889.24,7421.89) 1938.17,7421.89 1959.33,7400.74 1992.73,7400.74 R72.2@1996.9,7404.9
NetR73_1: R73.1 R74.2 U9.7 | length 231.1
  Top Layer w8: R74.2@2383.4,5157.15 2426.61,5157.15 2431.3,5161.84 2431.3,5184.72 2455.11,5208.53 U9.7@2484.63,5208.53
  Top Layer w15: R73.1@2288.95,5158.83 2290.63,5157.15 R74.2@2383.4,5157.15
NetR79_1: R79.1 R86.2 U10.6 | length 230.3
  Top Layer w15: U10.6@3219,4675.46 3286.46,4675.46 3325.92,4636 R86.2@3332.42,4636 R79.1@3433,4636
NetR81_1: R81.1 R85.2 U10.5 U10.7 U10.9 U10.11 | length 1083.4
  Top Layer w10: U10.11@2848.92,4575.46 2914.96,4575.46 2945.19,4605.68 2945.19,4651 2926.5,4669.69 2884.22,4669.69 U10.9@2878.45,4675.46 ; U10.9@2848.92,4675.46 2876.87,4675.46 2948.41,4747 3167.93,4747 U10.7@3189.47,4725.46 ; R81.1@3126,4844 3206.25,4844 3217.25,4833 3217.25,4727.2 U10.7@3219,4725.46 U10.7@3189.47,4725.46 ; U10.5@3219,4625.46 3146.73,4625.46 3126,4646.19 3126,4701.27 3145.41,4720.68 3194.24,4720.68 U10.7@3189.47,4725.46
NetR82_1: R82.1 R84.2 | length 125.6
  Bottom Layer w8: R84.2@2673.63,5522.97 2682.46,5522.97 2743.17,5583.67 2752.14,5583.67 R82.1@2767.63,5599.16
NetR83_1: R83.1 R84.1 R88.2 R89.2 U3.12 | length 439.9
  Top Layer w8: U3.12@2481.65,5638.47 2543.03,5638.47 2558.34,5653.79 v1(2558.83,5653.79)
  Bottom Layer w8: R88.2@2374.52,5603.17 2477.85,5603.17 R89.2@2572.97,5603.17 ; v1(2558.83,5653.79) 2572.97,5639.65 R89.2@2572.97,5603.17 ; R84.1@2673.63,5602.97 2672.52,5604.07 R89.2@2580.38,5604.07 2573.88,5604.07 R89.2@2572.97,5603.17
NetR87_1: R87.1 U3.13 U3.14 | length 165.7
  Top Layer w8: R87.1@2373.79,5519.5 2413.86,5519.5 2432.83,5538.47 U3.14@2481.65,5538.47 U3.13@2481.65,5588.47
NetR91_1: R91.1 R92.2 U10.4 | length 323.5
  Top Layer w15: U10.4@3219,4575.46 3379.74,4575.46 3403,4552.2 R92.2@3403,4514.5 3494.5,4514.5 R91.1@3495,4514
NetR94_1: R94.1 R98.2 U10.8 | length 193.2
  Top Layer w15: R94.1@2656.04,4725.81 2751.16,4725.81 R98.2@2751.35,4726 2751.9,4725.46 U10.8@2848.92,4725.45
NetR95_1: R95.1 R97.2 U3.7 U11.10 | length 463.2
  Top Layer w10: U3.7@2882.73,5838.47 2882.73,5897.74 2911.62,5926.62 v1(2950.36,5926.62) 2987.07,5926.62 3000.73,5912.96 R97.2@3000.73,5878.47 3012,5889.75 U11.10@3159.42,5889.75
  Bottom Layer w8: v1(2950.36,5926.62) 2950.36,5940.36 2985.5,5975.49 R95.1@2985.5,5981.99 R95.1@2985.86,5982.35
NetR96_2: R96.2 U3.6 U11.1 U11.2 U11.3 U11.4 U11.5 U11.6 U11.7 U11.8 U11.9 | length 731.7
  Top Layer w15: U3.6@2882.73,5788.47 2815.62,5788.47 v1(2815.22,5788.88) 2815.67,5789.33 2815.67,5885.8 2894.39,5964.52 3160.11,5964.52 3209.42,5915.2 U11.9@3209.42,5889.75
  Bottom Layer w8: v1(2815.22,5788.88) v1@2815.62,5788.47 ; R96.2@2890.59,5788.47 R96.2@2904.12,5802
  Bottom Layer w15: v1@2815.62,5788.47 R96.2@2890.59,5788.47
NetR101_1: R101.1 R104.2 U10.10 | length 194
  Top Layer w15: R101.1@2655.24,4624.57 R104.2@2751.35,4624.57 2752.24,4625.46 U10.10@2848.92,4625.46
NetR102_1: R102.1 R103.2 U3.9 | length 184.2
  Top Layer w8: R102.1@2373.79,5825.38 2381.86,5825.38 2420.62,5786.62 v1@2421.07,5786.17 ; v1(2420,5786) 2421.24,5787.24 2480.41,5787.24 U3.9@2481.65,5788.47
  Bottom Layer w8: R103.2@2379,5826 2380.79,5826 2420,5786.79 v1(2420,5786)
NetR102_2: R102.2 R105.1 U3.8 | length 247.7
  Top Layer w8: R105.1@2276.45,5898.03 2276,5897.59 2369.69,5897.59 R102.2@2373.79,5893.49 2455.5,5893.49 2481.65,5867.33 U3.8@2481.65,5838.47
NetR106_1: R106.1 U12.4 | length 105.8
  Top Layer w8: U12.4@1783.07,6612.51 R106.1@1888.92,6612.51
NetR106_2: R106.2 U3.10 | length 1404.4
  Top Layer w8: R106.2@1889.35,6548.8 1889.35,6125.13 2042.33,5972.15 2476.74,5972.15 2555.19,5893.7 2555.19,5755.04 2538.62,5738.47 U3.10@2481.65,5738.47
NetR111_1: R111.1 R112.2 TP29.1
NetR117_1: R117.1 R118.2 TP34.1
NetR129_2: R129.2 R131.2 U32.6 | length 232.3
  Top Layer w10: v1(460.12,4321) 514.87,4321 U32.6@515.12,4320.75
  Bottom Layer w10: R129.2@320.9,4377.45 320.9,4374.14 324.16,4377.4 R131.2@414.17,4377.4 420.67,4377.4 458.59,4339.49 458.59,4322.53 v1(460.12,4321)
NetR134_1: R134.1 R135.2 TP36.1
NetR140_2: R140.2 R141.2 | length 108.6
  Top Layer w8: R141.2@3272.65,2849 3264,2857.65 3264,2899.07 3298.26,2933.33 R140.2@3304.76,2933.33
NetR142_1: R142.1 R145.2 | length 115.2
  Bottom Layer w15: R142.1@3096.39,3125.05 3096.39,3012.97 R145.2@3098.62,3010.74
NetR143_2: R143.2 R144.1 U17.11 | length 199.7
  Top Layer w8: R144.1@2596,3038 2596.65,3038.65 R143.2@2596.65,3131 2605.65,3122 2637,3122 2649.81,3109.19 2693.81,3109.19 U17.11@2694,3109
NetR147_1: R147.1 R150.2 U21.3 | length 292.7
  Top Layer w15: v1(2805.97,1703.1) 2820.6,1688.47 U21.3@2882.73,1688.47
  Bottom Layer w15: v1(2805.97,1703.1) 2830.6,1678.47 R147.1@2882.73,1678.47 3002.44,1678.47 R150.2@3004.67,1676.24
NetR148_1: R148.1 R149.2 U17.3 | length 237.5
  Top Layer w8: U17.3@3105.56,3059.19 3106.71,3058.04 v1(3176.02,3058.04)
  Bottom Layer w8: v1(3176.02,3058.04) 3177.17,3056.89 3177.17,3044.08 3216.1,3005.14 R149.2@3216.1,2998.64 R148.1@3216.1,2908.04
NetR151_1: R151.1 R152.2 R153.2 U18.3 | length 350.6
  Top Layer w15: v1(2681.93,2391.98) 2711.41,2362.5 U18.3@2775.84,2362.5
  Bottom Layer w15: v1(2681.93,2391.98) 2681.93,2444.07 R151.1@2679,2447 2681.93,2447 R152.2@2773,2447 2773,2354.5 R153.2@2771.79,2353.29
NetR154_1: R154.1 R159.2 U18.1 | length 271.2
  Top Layer w8: v1(2705.05,2262.5) U18.1@2775.84,2262.5 2805.97,2262.5 2828.95,2239.51 R159.2@2887.51,2239.51
  Bottom Layer w8: R154.1@2647,2313.66 2653.5,2313.66 2704.66,2262.5 v1(2705.05,2262.5)
NetR156_2: R156.2 R159.1 U18.2 | length 296.8
  Top Layer w8: v1(2709.88,2310.41) 2773.75,2310.41 U18.2@2775.84,2312.5 2880.49,2312.5 R159.1@2887.51,2319.51
  Bottom Layer w8: v1(2709.88,2310.41) 2710.62,2311.15 2729.9,2311.15 2774.06,2267 R156.2@2774.06,2260.5 2778.39,2256.17 R156.2@2764.26,2242.04
NetR157_2: R157.2 R158.1 U18.11 | length 241.6
  Top Layer w20: R158.1@2243.57,2381.39 2244.76,2382.57 R157.2@2244.76,2463.33 ; R157.2@2244.76,2471.4 R157.2@2244.76,2463.33 ; U18.11@2374.76,2412.5 2327.5,2412.5 2276.67,2463.33 R157.2@2244.76,2463.33
NetR160_1: R160.1 R162.2 | length 95.9
  Bottom Layer w15: R162.2@3285.26,3204.04 3285.26,3283.74 R160.1@3296.69,3295.17
NetR161_1: R161.1 R162.1 R164.2 U17.5 | length 291.3
  Top Layer w15: U17.5@3105.56,3159.19 v1(3174.87,3159.19) 3209.9,3124.16 R161.1@3209.9,3117.66
  Bottom Layer w15: v1(3174.87,3159.19) 3177.17,3156.89 3180.61,3156.89 R164.2@3217.15,3120.35 ; R162.1@3217.15,3204.04 R164.2@3217.15,3120.35 ; R164.2@3217.15,3120.35 3217.15,3113.85 R164.2@3221,3110 3221,3116.5 R164.2@3217.15,3120.35
NetR163_1: R163.1 U17.6 U17.7 | length 196.9
  Top Layer w8: U17.7@3105.56,3259.19 U17.6@3105.56,3209.19 3174.55,3209.19 3200.71,3235.34 R163.1@3200.71,3276.27
NetR167_1: R167.1 U17.8 U17.9 | length 160.1
  Top Layer w8: R167.1@2596,3260 2596.81,3259.19 U17.8@2704.48,3259.19 ; U17.9@2704.48,3209.19 2704.48,3255.48 U17.8@2708,3259
NetR171_1: R171.1 R175.2 | length 137.6
  Bottom Layer w8: R171.1@2707.08,3203.44 2835.16,3203.44 R175.2@2841.87,3196.74
NetR173_2: R173.2 R174.1 U21.11 | length 201.3
  Top Layer w18: R174.1@2375.96,1801.59 2377.14,1800.41 R173.2@2377.14,1714.98 2383.84,1721.68 2410.34,1721.68 2427.14,1738.47 U21.11@2481.65,1738.47
NetR175_1: R175.1 R177.2 R178.2 U17.12 | length 305.9
  Top Layer w8: U17.12@2704.48,3059.19 2752.1,3059.19 v1(2773.8,3037.5)
  Bottom Layer w8: R178.2@2706.4,3037.5 v1(2773.8,3037.5) 2841.19,3037.5 R177.2@2841.87,3036.82 R175.1@2841.87,3128.63
NetR176_1: R176.1 U17.13 U17.14 | length 164.4
  Top Layer w8: R176.1@2596.96,2948.54 2607.61,2959.19 U17.14@2704.48,2959.19 U17.13@2704.48,3009.19 2704.48,3009.48 U17.13@2706,3011
NetR180_1: R180.1 R182.2 | length 96.2
  Bottom Layer w8: R180.1@2180,2229.19 2272.1,2229.19 R182.2@2275,2226.28
NetR181_1: R181.1 R182.1 R184.2 U18.12 | length 349.4
  Top Layer w15: U18.12@2374.76,2362.5 2375.51,2361.75 2465.4,2361.75 v1(2466.15,2361)
  Bottom Layer w15: R182.1@2275,2294.39 2378.55,2294.39 R184.2@2378.87,2294.07 2464.77,2294.07 2466.15,2295.45 v1(2466.15,2361)
NetR183_1: R183.1 U18.13 U18.14 | length 164.8
  Top Layer w8: R183.1@2275.06,2299.01 2281.56,2299.01 2318.07,2262.5 U18.14@2374.76,2262.5 U18.13@2374.76,2312.5
NetR185_3: R185.3 U22.8 | length 281
  Top Layer w8: U22.8@3187.43,2326.63 3187.43,2127.4 3215.73,2099.1 R185.3@3257.48,2099.1
NetR185_4: R185.4 U22.1 | length 176.4
  Top Layer w8: R185.4@3492.52,2199.1 3492.52,2299.04 3520.1,2326.63 U22.1@3557.51,2326.63
NetR186_1: R186.1 U18.6 U18.7 | length 174.8
  Top Layer w8: U18.7@2775.84,2562.5 U18.6@2775.84,2512.5 2898.95,2512.5 R186.1@2900.17,2511.28
NetR188_1: R188.1 R190.2 U23.7 | length 195.3
  Top Layer w8: R190.2@1259.5,3568.88 R190.2@1261.72,3571.1
  Top Layer w10: R188.1@1259.5,3484.36 R190.2@1259.5,3568.87 ; R190.2@1261.72,3571.1 1314.34,3571.1 1368.13,3571.1 U23.7@1368.98,3571.96
NetR189_1: R189.1 TP54.1 U23.4 | length 264.6
  Top Layer w8: U23.4@1828.82,3571.96 1829.4,3572.53 1888.6,3572.53 v1(1889.18,3573.11) 1889.36,3573.29 1889.36,3713.71 TP54.1@1889.55,3713.9
  Bottom Layer w8: R189.1@1826.35,3573.07 1826.39,3573.11 v1(1889.18,3573.11)
NetR191_2: R191.2 R197.2 U23.3 | length 286
  Top Layer w8: U23.3@1828.2,3523.17 1828.88,3522.48 1888.39,3522.48 v1(1889.08,3521.8) 1929.92,3521.8 1951.28,3543.16 1983.62,3543.16 R191.2@1989.83,3549.37
  Bottom Layer w8: v1(1889.08,3521.8) 1926.47,3521.8 1955.16,3550.49 R197.2@1989.61,3550.49
NetR192_1: R192.1 R195.2 | length 98.4
  Bottom Layer w8: R195.2@2253.15,2442 R195.2@2254,2442.85
  Bottom Layer w15: R192.1@2156,2442 R195.2@2253.15,2442
NetR193_2: R193.2 R199.2 U23.2 | length 282.1
  Top Layer w8: U23.2@1828.2,3473.17 1828.79,3472.58 1886.82,3472.58 v1(1887.41,3471.99) 1932.79,3471.99 1949.12,3455.66 1979.51,3455.66 R193.2@1988.51,3464.66
  Bottom Layer w8: v1(1887.41,3471.99) 1930.64,3471.99 1947.83,3454.8 1977.11,3454.8 R199.2@1987.02,3464.71
NetR194_1: R194.1 R195.1 R198.2 U18.10 | length 354.1
  Top Layer w8: v1(2312.66,2476.63) 2326.79,2462.5 U18.10@2374.76,2462.5
  Bottom Layer w8: R195.1@2254,2510.96 2262.07,2510.96 2296.41,2476.63 v1(2312.66,2476.63) ; R195.1@2254,2525.46 2259.53,2519.93 R198.2@2373.81,2519.93 2464.45,2519.93 R194.1@2464.85,2519.54
NetR196_1: R196.1 U18.8 U18.9 | length 167
  Top Layer w8: R196.1@2261,2554.58 2268.92,2562.5 U18.8@2374.76,2562.5 U18.9@2374.76,2512.5
NetR200_1: R200.1 R201.2 U24.7 | length 217.2
  Top Layer w8: R201.2@2383.76,1207.33 2389.16,1207.33 2438.9,1257.07 2483.17,1257.07 U24.7@2484.63,1258.53
  Top Layer w15: R200.1@2289.32,1209 2290.99,1207.33 R201.2@2383.76,1207.33
NetR206_1: R206.1 R208.2 | length 95.4
  Bottom Layer w8: R208.2@2669.49,1652.8 2761.88,1652.8 R206.1@2764.02,1650.66
NetR207_1: R207.1 R208.1 R211.2 R212.2 U21.12 | length 501.3
  Top Layer w8: v1(2418.98,1609.49) 2418.98,1655.94 2451.52,1688.47 U21.12@2481.65,1688.47
  Bottom Layer w8: R211.2@2363.79,1655.09 2370.29,1655.09 2415.89,1609.49 v1(2418.98,1609.49) 2465.85,1656.35 R207.1@2477.56,1656.35 2573.96,1656.35 R212.2@2574.22,1656.61 2580.72,1656.61 2641.99,1595.35 2641.99,1593.8 2662.25,1573.53 R208.1@2668.75,1573.53
NetR209_1: R209.1 U21.13 U21.14 | length 196.6
  Top Layer w8: R209.1@2363.79,1549.5 2464.11,1549.5 2481.65,1567.04 U21.14@2481.65,1588.47 U21.13@2481.65,1638.47
NetR213_1: R213.1 R216.2 U25.6 | length 230.3
  Top Layer w15: U25.6@3215.6,725.24 3283.07,725.24 3322.52,685.79 3329.02,685.79 R213.1@3429.61,685.79
NetR214_1: R214.1 R215.2 U25.5 U25.7 U25.9 U25.11 | length 1079.2
  Top Layer w10: U25.11@2845.52,625.24 2911.56,625.24 2941.79,655.47 2941.79,700.79 2919.3,723.28 2847.49,723.28 U25.9@2845.52,725.24 ; U25.9@2878.36,725.83 2952.83,800.3 3166.92,800.3 U25.7@3188.89,778.02 ; R214.1@3122.61,893.79 3202.86,893.79 3213.86,882.79 3213.86,776.99 3217.71,773.13 3144.69,773.13 3122.61,751.05 3122.61,695.97 3143.34,675.24 U25.5@3215.6,675.24
NetR218_1: R218.1 R219.2 U25.4 | length 323.5
  Top Layer w15: U25.4@3215.6,625.24 3376.35,625.24 3399.61,601.98 3399.61,564.28 3491.11,564.28 R218.1@3491.61,563.79
NetR220_1: R220.1 R222.2 U21.7 U26.10 | length 420.6
  Top Layer w10: U21.7@2882.73,1888.47 2882.73,1913.65 2911.54,1942.46 v1(2939,1942.46) 2999.8,1942.46 R222.2@3000.72,1941.54 3156.64,1941.54 U26.10@3158.43,1939.74
  Bottom Layer w8: v1(2939,1942.46) 2939,1987.5 2978,2026.5 R220.1@2978,2033
NetR221_2: R221.2 U21.6 U26.1 U26.2 U26.3 U26.4 U26.5 U26.6 U26.7 U26.8 U26.9 | length 730.7
  Top Layer w15: U21.6@2882.73,1838.47 2819.7,1838.47 v1(2799,1859.18) 2799,1921.9 2892.51,2015.41 3159.21,2015.41 3207.54,1967.09 U26.9@3207.54,1940.64
  Bottom Layer w6: R221.2@2877.15,1859.18 R221.2@2879.81,1861.84
  Bottom Layer w8: v1(2799,1859.18) R221.2@2877.15,1859.18
NetR225_1: R225.1 R226.2 U25.8 | length 193.2
  Top Layer w15: R225.1@2652.65,775.6 2747.77,775.6 2747.96,775.79 2748.5,775.24 U25.8@2845.52,775.24
NetR227_1: R227.1 R228.2 U21.9 | length 192.2
  Top Layer w8: R227.1@2383.92,1876.35 v1(2422.35,1837.92) 2422.63,1838.2 2481.37,1838.2 U21.9@2481.65,1838.47
  Bottom Layer w8: R228.2@2370,1874.35 2404.46,1874.35 2422.35,1856.46 v1(2422.35,1837.92)
NetR227_2: R227.2 R229.1 U21.8 | length 254.4
  Top Layer w8: R229.1@2277.42,1944.01 2287.42,1954.01 2448.44,1954.01 2481.65,1920.8 U21.8@2481.65,1888.47
NetR231_1: R231.1 U27.4 | length 100.6
  Top Layer w8: U27.4@1783.07,2662.52 1879.49,2662.52 R231.1@1882.44,2665.46
NetR231_2: R231.2 U21.10 | length 1401
  Top Layer w8: R231.2@1882.44,2597.35 1882.44,2195.15 2027.05,2050.53 2418.96,2050.53 2570.2,1899.29 2570.2,1807.02 2551.65,1788.47 U21.10@2481.65,1788.47
NetR232_1: R232.1 R233.2 U25.10 | length 194
  Top Layer w15: R232.1@2651.84,674.36 2747.96,674.36 2748.85,675.24 U25.10@2845.52,675.24
NetR238_1: R238.1 R239.2 TP65.1
NetR244_1: R244.1 R246.2 TP69.1
NetR247_2: R247.2 U32.10 | length 101.5
  Top Layer w10: R247.2@1120.24,4269.28 R247.2@1136.98,4286.01
  Top Layer w12: U32.10@1042.12,4270.75 R247.2@1120,4270.75
NetR258_2: R258.2 R267.2 U33.6 | length 223.2
  Top Layer w12: v1@464.75,370.55 514.61,370.55 U33.6@514.87,370.29
  Bottom Layer w12: R258.2@320.54,427.12 320.54,423.82 323.81,427.08 R267.2@413.82,427.08 ; R267.2@420.32,427.08 460,387.4 460,374.22 v1@455.95,370.17
  other v1: 459.86,370.55
NetR261_1: R261.1 R262.2 TP71.1
NetR269_2: R269.2 U33.10 | length 101.5
  Top Layer w10: R269.2@1119.99,318.82 R269.2@1136.72,335.56
  Top Layer w12: U33.10@1041.87,320.29 R269.2@1119.74,320.29
NetU3_1: U3.1 U3.2 | length 50
  Top Layer w8: U3.1@2882.73,5538.47 U3.2@2882.73,5588.47
NetU9_8: U9.8 U9.9 | length 50
  Top Layer w8: U9.9@2484.63,5108.53 U9.8@2484.63,5158.53
NetU21_1: U21.1 U21.2 | length 50
  Top Layer w8: U21.1@2882.73,1588.47 U21.2@2882.73,1638.47
NetU24_8: U24.8 U24.9 | length 50
  Top Layer w8: U24.9@2484.63,1158.53 U24.8@2484.63,1208.53
P2V5: C75.1 C76.1 R142.2 R148.2 R151.2 R160.2 R165.1 R166.2 R171.2 R180.2 R192.2 U19.10 U20.2 | length 38.4
  Top Layer w8: v1(871.98,2692.06) 880.19,2683.85 906.85,2683.85 U20.2@906.97,2683.73
  other v1: 970.52,3178.63 1003.77,3178.63 970.52,3205.64 1003.77,3205.64
P3V3: C14.1 C17.1 C18.1 C33.1 D1.1 J6.4 J16.1 R39.2 R41.2 R46.2 R60.2 R61.2 U6.37 U6.48 U8.1 U8.10 | length 0.3
  Top Layer w8: U6.48@881.38,6588.46 U6.48@881.61,6588.23
  other v1: 728.27,6468.29 698.86,6469.11 698.86,6506.83 727.75,6507.35 943.99,6528.99 916.74,6530.2 917.47,6555.12 944.21,6555.78 534.31,6856.27 563.12,6856.27 1883.87,7297.09 1188.11,7299.84 1226.56,7299.84 1265.01,7299.84 1321.33,7305.1 1355.5,7305.1 1883.87,7326.43 1320.19,7335.78 1355.5,7335.78 1883.22,7353.34
P3V3(b): C8.1 J20.1 R32.2 U4.13
  other v1: 1258.63,6870.55 1301.42,6870.55 1258.63,6897 1301.42,6897 1196.87,7202.82 1222.2,7202.82 1195.87,7229.82 1222.2,7229.82
P3V3(m): C77.1 C79.1 C80.1 C92.1 D13.1 J27.4 J36.1 R170.2 R172.2 R179.2 R188.2 R189.2 U20.37 U20.48 U23.1 U23.10 | length 0.3
  Top Layer w8: U20.48@881.38,2637.46 U20.48@881.61,2637.23
  other v1: 728.27,2518.29 698.86,2519.11 698.86,2556.83 727.75,2557.35 947.09,2568.39 919.85,2569.6 920.58,2594.52 947.31,2595.18 539.62,2902.72 568.43,2904.74 1883.19,3340.66 1188.01,3349.8 1226.46,3349.8 1264.91,3349.8 1883.19,3370 1320.09,3384.95 1355.4,3385.74 1882.23,3401.09
P3V3(mb): J40.1 R165.2
  other v1: 1129.44,3239.9 1162.69,3239.9 1129.44,3266.91 1162.69,3266.91
P5V0: C35.1 C49.1 C50.1 C58.1 C59.1 J15.1 J17.3 L1.1 R9.2 R11.2 R78.2 R81.2 R90.2 R93.2 R100.2 R125.2 U10.3 U13.2 U13.3 U13.4 U32.1 U32.2 U32.3 U32.4
  other v1: 2958.2,4159.15 2711.35,4159.59 2836,4159.59 590.03,4169.2 2711.35,4193.28 2836,4193.28 2958.2,4193.28 588.75,4201.01 3342.37,4488.14 3341.67,4515.27 412.46,4562.57 442.9,4562.57 412.46,4592.86 442.9,4592.86 2963.36,4823.83 2991.5,4823.83 2963.36,4862.75 2991.5,4862.75 291.89,5087.87 326.11,5087.87 291.89,5119.83 326.11,5119.83 2861,5463.5 2896,5463.5 2861,5492.45 2896,5492.45 3367,6848.68 3367,6880.5 3367,6910
P5V0(m): C98.1 C109.1 C110.1 C118.1 C119.1 J35.1 J37.3 L2.1 R147.2 R210.2 R214.2 R217.2 R223.2 R230.2 R256.2 U25.3 U28.2 U28.3 U28.4 U33.1 U33.2 U33.3 U33.4
  other v1: 2955.68,209.15 2708.15,209.6 2834.55,209.6 589.77,218.75 2708.15,243.28 2832.8,243.28 2955,243.28 590.19,250.81 3345.69,537.8 3346.04,563.8 412.21,612.12 442.64,612.12 412.21,642.41 442.64,642.41 2959.54,873.36 2988.11,873.36 2959.23,912.54 2988.11,912.54 290.94,1146.82 325.29,1146.82 290.21,1178.68 324.56,1178.68 2864,1520.53 2900.17,1520.89 2864,1549 2900.17,1549
P5V0(m,Op): C82.2 C87.1 C128.1 C129.1 C133.1 U17.4 U21.4 U22.6 U31.2 U31.3 U31.4 U33.13 U33.14 U33.15 U33.16 | length 341.1
  Top Layer w20: U21.4@2882.73,1738.47 2912.86,1738.47 2936.35,1714.98 2999.56,1714.98 v1(3063.59,1714.98) ; C87.1@3075.12,2372.86 3081.62,2372.86 3096.62,2387.86 3096.62,2415.03 3108.21,2426.63 U22.6@3187.43,2426.63
  other v1: 1213.84,513.74 1245.78,513.74 1212.82,547.51 1245.78,547.51 3115,2426.63 3041,3092 3041,3121
P5V0(mR): C100.1 C101.1 C103.1 R237.2 U27.1
  other v1: 937.23,2011.26 965.19,2011.92 937.23,2047.1 965.2,2046.55 1766.75,2427.58 1804.89,2427.58 1765.45,2459.45 1803.59,2459.45
P5V0(Op): C3.2 C24.1 C61.1 C68.1 C69.1 U1.4 U3.4 U7.6 U16.2 U16.3 U16.4 U32.13 U32.14 U32.15 U32.16 | length 236.9
  Top Layer w20: C24.1@3083.37,6325.7 3083.37,6374.82 3101.1,6392.56 v1(3263.82,6392.56)
  other v1: 1224.88,4470.25 1256.82,4470.25 1223.86,4504.02 1256.82,4504.02 3087.85,5667.88 3054.85,5668.88 3086.85,5693.88 3055.85,5694.88 3041,7040 3041,7071
P5V0(R): C5.1 C6.1 C40.1 C41.1 C43.1 R3.2 R14.2 R24.2 R33.2 R40.2 R48.2 R63.2 R110.2 U4.2 U12.1
  other v1: 942.14,5965.64 968.02,5965.64 942.14,5994.44 968.02,5994.44 1766.12,6383.72 1804.12,6383.72 1766.12,6412.16 1804.12,6412.16 2114.79,6819.4 2145.83,6819.4 2114.79,6849.39 2145.83,6849.39 2114.79,6879.61 2145.83,6879.61
"Power Sequencing": R128.1 R129.1 U6.28 | length 4315.5
  Top Layer w8: v1(610.44,6852.28) 610.44,6787.68 626.59,6771.53 U6.28@639.25,6771.53 U6.28@639.39,6771.39
  Signal w10: v1(610.44,6852.28) 640.15,6822.57 640.15,6589.33 682.7,6546.79 760.13,6546.79 1725.57,5581.35 v1(1725.57,5576.28)
  Bottom Layer w10: R129.1@320.9,4457.45 320.9,4602.61 359.72,4641.43 1474.39,4641.43 1678.5,4845.54 1678.5,5529.21 v1(1725.57,5576.28) 1800.76,5576.28 1802.74,5578.26 R128.1@1802.96,5578.04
